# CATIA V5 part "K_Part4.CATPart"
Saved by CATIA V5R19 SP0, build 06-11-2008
Part number: Part4
Bounding box of the stored display mesh (mm): x -46.325 to 46.325, y 36.474 to 72.124, z 13.305 to 58.305
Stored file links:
  G:\Khaled_CFAO_2011\SIL\SIL_GR2\ctanaphiko\Khaled\CAD_ThinkMOTION\K_Part4.CATPart
  G:\Khaled_CFAO_2011\SIL\SIL_GR2\ctanaphiko\CATIA\Conception_Tripod.CATProduct
  G:\Khaled_CFAO_2011\SIL\SIL_GR2\ctanaphiko\Khaled\CAD_ThinkMOTION\K_Leg_Level1.CATPart
  G:\Khaled_CFAO_2011\SIL\SIL_GR2\ctanaphiko\CATIA\Squelette.CATPart
  G:\Khaled_CFAO_2011\SIL\SIL_GR2\ctanaphiko\Khaled\CAD_ThinkMOTION\K_Leg_Level2.CATPart
  G:\Khaled_CFAO_2011\SIL\SIL_GR2\ctanaphiko\CATIA\Part14.CATPart
  G:\Khaled_CFAO_2011\SIL\SIL_GR2\ctanaphiko\Khaled\CAD_ThinkMOTION\K_Part8.CATPart
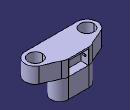
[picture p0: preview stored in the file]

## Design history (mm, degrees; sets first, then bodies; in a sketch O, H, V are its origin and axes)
External parameters (linked from other documents)
  External.Dia_Leg_Step2 = 18 mm
  External.Dia_Leg_Step1 = 18 mm
  External.Width_Leg_Support = 75 mm
AxisSystem1: origin (0, 0, 0), X (1, 0, 0), Y (0, 1, 0), Z (0, 0, 1)
Sketch1 on Plane3, origin (0, 0, 38.3053), H (1, 0, 0), V (0, 1, 0)
  point P1 (40, 93.0116)
  point P2 (-40, 93.0116)
  construction line L1 (-19.8, 54.3613) -> (19.8, 54.3613)
  point P5 (20.5894, 72.677)
  construction line L2 (-33.0316, 49.774) -> (33.0316, 49.774)
  point P6 (-33.0316, 49.774)
  point P7 (33.0316, 49.774)
  construction line L3 (-33.0316, 63.074) -> (33.0316, 63.074)
  line L4 (33.0316, 36.474) -> (-33.0316, 36.474)
  arc A1 centre (33.0316, 49.774) radius 13.3 from (39.713, 61.274) to (33.0316, 36.474) cw
  arc A2 centre (-33.0316, 49.774) radius 13.3 from (-33.0316, 36.474) to (-39.713, 61.274) cw
  point P8 (-33.0316, 63.074)
  point P9 (33.0316, 63.074)
  construction line L5 (33.0316, 71.282) -> (33.0316, 71.6924)
  construction line L6 (-33.0316, 71.282) -> (-33.0316, 71.6924)
  point P16 (-39.713, 61.274)
  point P17 (39.713, 61.274)
  reference projected line E1 (-28.7548, 49.774) -> (28.7548, 49.774) from Line1
  projected circle E2 centre (-33.0316, 49.774) radius 9 from edge of DatumCurve1
  projected circle E3 centre (33.0316, 49.774) radius 9 from edge of DatumCurve2
  construction line L7 (-13.2127, 61.024) -> (13.2127, 61.024)
  point P18 (-13.2127, 61.024)
  point P19 (13.2127, 61.024)
  line L8 (-13.2127, 72.124) -> (13.2127, 72.124)
  arc A3 centre (13.2127, 61.024) radius 11.1 from (13.2127, 72.124) to (19.9125, 69.874) cw
  arc A4 centre (-13.2127, 61.024) radius 11.1 from (-19.9125, 69.874) to (-13.2127, 72.124) cw
  reference projected point E4 (-13.2127, 61.024) from Point3
  reference projected point E5 (13.2127, 61.024) from Point1
  point P22 (-19.9125, 69.874)
  line L9 (-19.9125, 69.874) -> (-39.713, 61.274)
  point P23 (19.9125, 69.874)
  line L10 (39.713, 61.274) -> (19.9125, 69.874)
  reference projected point E6 (33.0316, 49.774) from Point4
  reference projected point E7 (-33.0316, 49.774) from Point5
  distance L2 L3 = 13.3 {= External.Dia_Leg_Step1/2 *1.2+External.Width_Leg_Support  /30}
  distance P16 L2 = 11.5 {= External.Dia_Leg_Step1/2+External.Width_Leg_Support /30}
  distance P17 L2 = 11.5 {= Sketch1.distance(P16 L2)}
  distance L7 L8 = 11.1 {= External.Dia_Leg_Step2 /2*1.15+External.Width_Leg_Support  /100}
  distance P22 L8 = 2.25 {= External.Dia_Leg_Step2 /2/4}
  distance P23 L8 = 2.25 {= External.Dia_Leg_Step2  /2/4}
  horizontal: L2 H, L7 H
  tangency: A1 L3, A2 L3, A1 L4, A2 L4, A3 L8, A4 L8
  vertical: L5 V, L6 V
  coincidence: A1 P9, L5 P9, A2 P8, L6 P8, L2 E1, P18 E4, P19 E5, P7 E6, P6 E7
Pad1: profile Sketch1, direction (0, 0, 1), length 20
Set1 "Plan"
  Plane1: type OffsetPt, RefPlane ZX plane of AxisSystem1, RefPoint Point2
  Plane2: type Offset, RefPlane Plane1, Offset -1.5 {= (1mm-External.Dia_Leg_Step2 /12)*3}, reversed
Set2
  Plane3 "Plan_S1": linked copy from another document
  DatumCurve1: linked copy from another document
  DatumCurve2: linked copy from another document
  Point1: linked copy from another document
  DatumCurve3 to DatumCurve6: linked copy from another document
  DatumSurface1: linked copy from another document
  DatumPoint1: linked copy from another document
  Line1: linked copy from another document
  Point2 to Point5: linked copy from another document
Body1
  Sketch2 on Plane3, origin (0, 0, 38.3053), H (1, 0, 0), V (0, 1, 0)
    circle A1 centre (0, 69.024) radius 1
    point P3 (0, 69.024)
    reference projected point E2 (0, 69.024) from vertex of DatumPoint1
    construction line L1 (-13.2127, 61.024) -> (13.2127, 61.024)
    line L2 (-13.2127, 72.124) -> (13.2127, 72.124)
    line L3 (13.2127, 49.924) -> (-13.2127, 49.924)
    arc A2 centre (13.2127, 61.024) radius 11.1 from (13.2127, 72.124) to (13.2127, 49.924) cw
    arc A3 centre (-13.2127, 61.024) radius 11.1 from (-13.2127, 49.924) to (-13.2127, 72.124) cw
    circle A4 centre (-13.2127, 61.024) radius 9
    circle A5 centre (13.2127, 61.024) radius 9
    radius A1 = 1
    distance L1 L2 = 11.1 {= External.Dia_Leg_Step2  *1.15/2+External.Width_Leg_Support  /100}
    radius A4 = 9 {= External.Dia_Leg_Step2 /2}
    radius A5 = 9 {= External.Dia_Leg_Step2 /2}
    coincidence: P3 V, P3 E2
    horizontal: L1 H
    tangency: A2 L2, A3 L2, A2 L3, A3 L3
  Sketch3 on Plane3, origin (0, 0, 58.3053), H (1, 0, 0), V (0, 1, 0)
    line L1 (-16.6453, 70.4745) -> (16.6453, 70.4745)
    arc A1 centre (16.6453, 63.5745) radius 6.9 from (16.6453, 70.4745) to (16.6453, 56.6745) cw
    line L2 (16.6453, 56.6745) -> (-16.6453, 56.6745)
    arc A2 centre (-16.6453, 63.5745) radius 6.9 from (-16.6453, 56.6745) to (-16.6453, 70.4745) cw
    reference projected line E1 (-40.8632, 63.5745) -> (40.8632, 63.5745) from edge of DatumCurve3
    circle A3 centre (0, 68.5745) radius 1
    point P9 (0, 68.5745)
    reference projected point E2 (0, 68.5745) from vertex of DatumPoint1
    projected circle E3 centre (-16.3453, 63.5745) radius 6 from edge of DatumCurve5
    projected circle E4 centre (16.3453, 63.5745) radius 6 from edge of DatumCurve4
    construction line L3 (35.3577, 63.5745) -> (-46.2171, 63.5745)
    point P10 (35.3577, 63.5745)
    reference projected circle E5 centre (16.3453, 63.5745) radius 6 from edge of DatumCurve4
    point P12 (22.3453, 63.5745)
    point P13 (10.3453, 63.5745)
    point P14 (-22.3453, 63.5745)
    point P15 (-10.3453, 63.5745)
    point P16 (-23.5453, 63.5745)
    point P17 (23.5453, 63.5745)
    point P18 (16.3453, 63.5745)
    point P19 (-16.3453, 63.5745)
    distance L1 L2 = 20.7 {= External.Dia_Leg_Step2 *1.15}
    distance L1 E1 = 10.35 {= Sketch3.distance(L1 L2) /2}
    radius A3 = 1
    distance P19 P16 = 10.8 {= External.Dia_Leg_Step2 /2*1.2}
    distance P18 P17 = 10.8 {= External.Dia_Leg_Step2 /2*1.2}
    horizontal: L1 H, L2 H, L3 H
    tangency: A1 L1, L2 A1, A2 L1, A2 L2
    coincidence: P9 V, P9 E2, P10 E1, L3 P12, E5 P12, L3 P13, E5 P13, E3 P14, L3 P14, E3 P15, L3 P15, L3 P16, A2 P16, L3 P17, A1 P17
    concentricity: P18 E4, P19 E3
  Sketch4 on Plane3, origin (0, 0, 58.3053), H (1, 0, 0), V (0, 1, 0)
    line L1 (-16.6453, 70.4745) -> (16.6453, 70.4745)
    arc A1 centre (16.6453, 63.5745) radius 6.9 from (16.6453, 70.4745) to (16.6453, 56.6745) cw
    line L2 (16.6453, 56.6745) -> (-16.6453, 56.6745)
    arc A2 centre (-16.6453, 63.5745) radius 6.9 from (-16.6453, 56.6745) to (-16.6453, 70.4745) cw
    reference projected line E1 (-40.8632, 63.5745) -> (40.8632, 63.5745) from edge of DatumCurve3
    circle A3 centre (0, 68.5745) radius 1
    point P9 (0, 68.5745)
    reference projected point E2 (0, 68.5745) from vertex of DatumPoint1
    projected circle E3 centre (-16.3453, 63.5745) radius 6 from edge of DatumCurve5
    projected circle E4 centre (16.3453, 63.5745) radius 6 from edge of DatumCurve4
    construction line L3 (35.3577, 63.5745) -> (-46.2171, 63.5745)
    point P10 (35.3577, 63.5745)
    reference projected circle E5 centre (16.3453, 63.5745) radius 6 from edge of DatumCurve4
    point P12 (22.3453, 63.5745)
    point P13 (10.3453, 63.5745)
    point P14 (-22.3453, 63.5745)
    point P15 (-10.3453, 63.5745)
    point P16 (-23.5453, 63.5745)
    point P17 (23.5453, 63.5745)
    point P18 (16.3453, 63.5745)
    point P19 (-16.3453, 63.5745)
    distance L1 L2 = 20.7 {= External.Dia_Leg_Step2 *1.15}
    distance L1 E1 = 10.35 {= Sketch4.distance(L1 L2) /2}
    radius A3 = 1
    distance P19 P16 = 10.8 {= External.Dia_Leg_Step2 /2*1.2}
    distance P18 P17 = 10.8 {= External.Dia_Leg_Step2 /2*1.2}
    horizontal: L1 H, L2 H, L3 H
    tangency: A1 L1, L2 A1, A2 L1, A2 L2
    coincidence: P9 V, P9 E2, P10 E1, L3 P12, E5 P12, L3 P13, E5 P13, E3 P14, L3 P14, E3 P15, L3 P15, L3 P16, A2 P16, L3 P17, A1 P17
    concentricity: P18 E4, P19 E3
  Pad2: profile Sketch2, direction (0, 0, -1), length 25
  Sketch5 on Plane3, origin (0, 0, 38.3053), H (1, 0, 0), V (0, 1, 0)
    construction line L1 (-13.2127, 61.024) -> (13.2127, 61.024)
    point P1 (-13.2127, 61.024)
    point P2 (13.2127, 61.024)
    line L2 (-13.2127, 71.374) -> (13.2127, 71.374)
    line L3 (13.2127, 50.674) -> (-13.2127, 50.674)
    arc A1 centre (13.2127, 61.024) radius 10.35 from (13.2127, 71.374) to (13.2127, 50.674) cw
    arc A2 centre (-13.2127, 61.024) radius 10.35 from (-13.2127, 50.674) to (-13.2127, 71.374) cw
    reference projected point E1 (-13.2127, 61.024) from Point3
    reference projected point E2 (13.2127, 61.024) from Point1
    distance L1 L2 = 10.35 {= External.Dia_Leg_Step2 /2*1.15}
    horizontal: L1 H
    tangency: A1 L2, A2 L2, A1 L3, A2 L3
    coincidence: P1 E1, P2 E2
  Pad3: profile Sketch5, direction (0, 0, -1), length 2
Body2 (main body)
  Plane4: type Offset, RefPlane Plane3, Offset 20
  Sketch6 on Plane2, origin (0, 62.524, 0), H (-1, 0, 0), V (0, 0, 1)
    line L1 (-12.5, 56.3053) -> (12.5, 56.3053)
    line L2 (12.5, 56.3053) -> (12.5, 38.3053)
    line L3 (12.5, 38.3053) -> (-12.5, 38.3053)
    line L4 (-12.5, 38.3053) -> (-12.5, 56.3053)
    reference intersected line E1 through (0, 58.3053) direction (-1, 0) from Plane4
    reference intersected line E2 through (0, 38.3053) direction (-1, 0) from Plane3
    distance L4 L2 = 25 {= External.Width_Leg_Support /3}
    distance L2 V = 12.5 {= Sketch6.distance(L4 L2) /2}
    distance L1 E1 = 2
    horizontal: L1 H, L3 H
    vertical: L2 V, L4 V
    coincidence: L3 E2
  Pocket1: profile Sketch6, direction (0, 1, 0), through (limit type 3)
  Sketch7 on face of Pocket1 from Sketch6.L4, origin (12.5, 0, 0), H (0, -1, 0), V (0, 0, 1)
    construction line L1 (-67.524, 47.3053) -> (-66.024, 47.3053)
    line L2 (-67.524, 48.8053) -> (-66.024, 48.8053)
    line L3 (-66.024, 45.8053) -> (-67.524, 45.8053)
    arc A1 centre (-66.024, 47.3053) radius 1.5 from (-66.024, 48.8053) to (-66.024, 45.8053) cw
    arc A2 centre (-67.524, 47.3053) radius 1.5 from (-67.524, 45.8053) to (-67.524, 48.8053) cw
    reference projected line E1 (-67.7175, 38.3053) -> (-76.4624, 38.3053) from edge [face of Pocket1 from Sketch6.L4 | start face of Pad1]
    reference intersected line E2 through (-62.524, 0) direction (0, -1) from Plane2
    reference intersected line E3 through (-62.524, 0) direction (0, -1) from Plane2
    reference intersected line E4 through (0, 38.3053) direction (-1, 0) from Plane3
    reference intersected line E5 through (0, 58.3053) direction (-1, 0) from Plane4
    distance L1 L2 = 1.5
    distance L1 E1 = 9 {= (Sketch7.distance(E4 E5) -2mm)/2}
    distance E2 A1 = 2
    distance E3 A2 = 6.5 {= 3.5mm+Sketch7.distance(L1 L2) *2}
    distance E4 E5 = 20 (reference)
    horizontal: L1 H
    tangency: A1 L2, A2 L2, A1 L3, A2 L3
  Pocket2: profile Sketch7, direction (1, 0, 0), length 2
  Sketch8 on face of Pocket1 from Sketch6.L2, origin (-12.5, 0, 0), H (0, 1, 0), V (0, 0, 1)
    construction line L1 (66.024, 47.3053) -> (67.524, 47.3053)
    line L2 (66.024, 48.8053) -> (67.524, 48.8053)
    line L3 (67.524, 45.8053) -> (66.024, 45.8053)
    arc A1 centre (67.524, 47.3053) radius 1.5 from (67.524, 48.8053) to (67.524, 45.8053) cw
    arc A2 centre (66.024, 47.3053) radius 1.5 from (66.024, 45.8053) to (66.024, 48.8053) cw
    reference projected line E1 (67.7175, 38.3053) -> (76.4624, 38.3053) from edge [start face of Pad1 | face of Pocket1 from Sketch6.L2]
    reference intersected line E2 through (62.524, 0) direction (0, 1) from Plane2
    reference intersected line E3 through (62.524, 0) direction (0, 1) from Plane2
    reference intersected line E4 through (0, 38.3053) direction (-1, 0) from Plane3
    reference intersected line E5 through (0, 58.3053) direction (-1, 0) from Plane4
    distance L1 L2 = 1.5
    distance L1 E1 = 9 {= (Sketch8.distance(E4 E5) -2mm) /2}
    distance A1 E3 = 6.5 {= 3.5mm+Sketch8.distance(L1 L2) *2}
    distance A2 E2 = 2
    distance E4 E5 = 20 (reference)
    horizontal: L1 H
    tangency: A1 L2, A2 L2, A1 L3, A2 L3
  Pocket3: profile Sketch8, direction (-1, 0, 0), length 2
